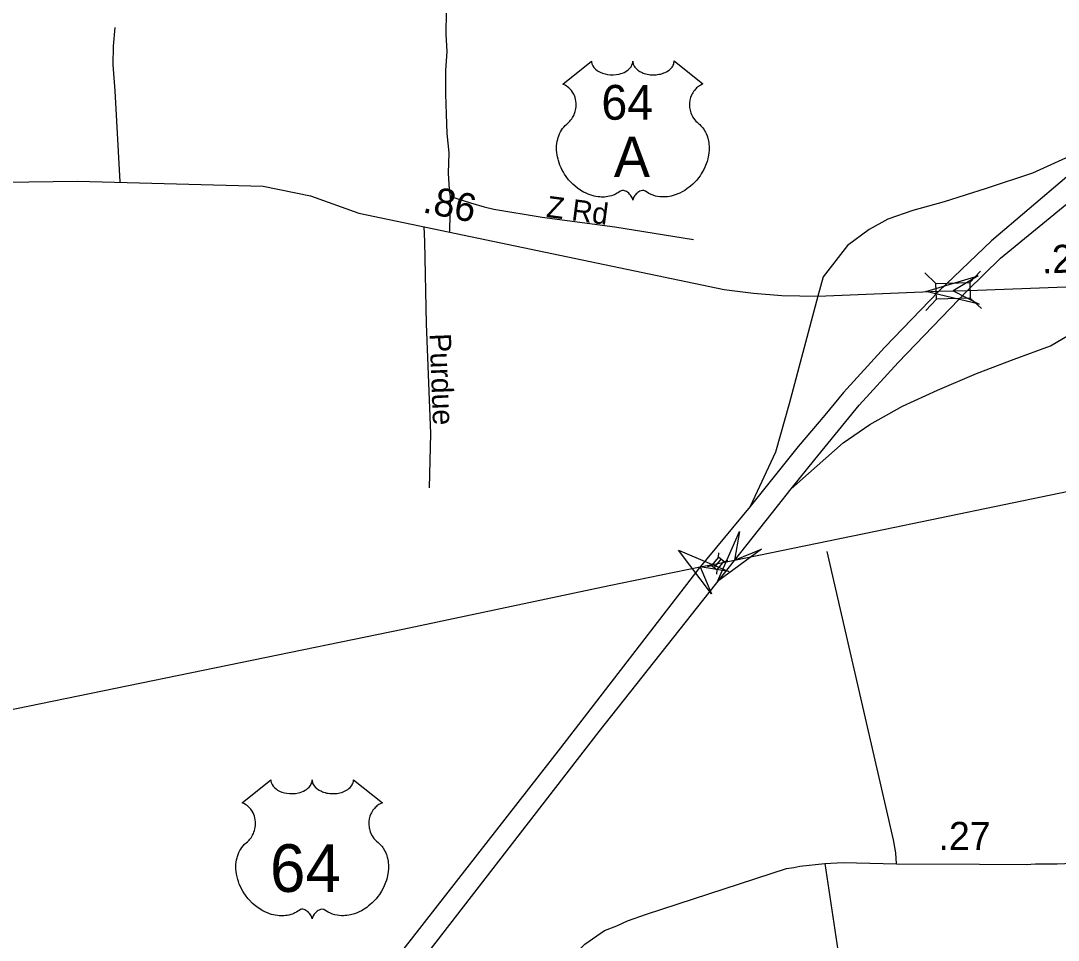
# Model space of a CAD drawing. Extents: x 2220236 to 2384410, y 720751 to 894131.
# Drawn here: x 2294303 to 2298927, y 806601 to 810700 of the extents above; entities that cross this region are included whole.
import ezdxf

# ---------------------------------------------------------------- set-up
doc = ezdxf.new("R2010")
doc.units = 0
for name, color, linetype in [('Exist Railroad Mainline', 7, 'Continuous'), ('Exist Road Non-System Type 51', 7, 'Continuous'), ('Exist Road Non-System Type 51 Label', 7, 'Continuous'), ('Exist Road Primary Interstate Structure Standard Bridge CELL', 7, 'Continuous'), ('Exist Road Primary US Attributed', 7, 'Continuous'), ('Exist Road Primary US Divided Attributed', 7, 'Continuous'), ('Exist Road Primary US Mileage Hundredths English Label', 7, 'Continuous'), ('Exist Road Primary US Ramp 1 Lane  Attributed', 7, 'Continuous'), ('Exist Road Primary US Shield CELL', 7, 'Continuous'), ('Exist Road Primary US Shield Number Label', 7, 'Continuous'), ('Exist Road Primary US Structure Standard Bridge CELL', 7, 'Continuous'), ('Exist Road Secondary Mileage Hundredths English Label', 7, 'Continuous'), ('Exist Road Secondary Structure Standard Bridge Attributed CELL', 7, 'Continuous'), ('Exist Road Secondary Type 10 Attributed', 7, 'Continuous'), ('Exist Road Secondary Type 51 Attributed', 7, 'Continuous')]:
    doc.layers.add(name, color=color, linetype=linetype)

msp = doc.modelspace()

# ---------------------------------------------------------------- linework, layer by layer
at = {"layer": 'Exist Railroad Mainline'}
for points in [[(2297485.2, 808295.4), (2298113, 808425.3), (2299547.1, 808722.5), (2300514.6, 808918.9), (2300696.2, 808954.7), (2300734.1, 808967.3), (2300795.9, 808977.8), (2300861.9, 808984.5), (2300935.6, 808997.3), (2301005.4, 809006.2), (2301137.4, 809017.6), (2301359.2, 809029.8), (2301569, 809020.2), (2302025, 809015), (2302689, 808990.3), (2303650.7, 808970.6)], [(2293833.8, 807542.5), (2296006.8, 807988.7), (2296926.1, 808182.5), (2297331, 808265.1), (2297409.9, 808280.9), (2297485.2, 808295.4)]]:
    msp.add_lwpolyline(points, dxfattribs=at)
at = {"layer": 'Exist Road Non-System Type 51'}
msp.add_line((2296216.3, 809760.3), (2296218.4, 809916.5), dxfattribs=at)
for points in [[(2296218.4, 809916.5), (2296214.2, 809948.2), (2296210, 810020), (2296212.1, 810110.8), (2296203.7, 810197.4), (2296201.5, 810284), (2296197.3, 810372.7), (2296197.3, 810478.3), (2296203.7, 810562.7), (2296199.4, 810638.8), (2296200.5, 810743.3), (2296200.5, 810853.1), (2296187.8, 810962.9), (2296187.8, 811102.3), (2296194.2, 811174.1)], [(2294722, 810669.4), (2294714.7, 810587.4), (2294713.5, 810503.4), (2294722.5, 810387.5), (2294744.4, 809981.9)], [(2296218.4, 809916.5), (2296308.1, 809889), (2296368.3, 809869.9), (2296412.5, 809860.3), (2296626.6, 809824.6), (2296951.1, 809782), (2297302.1, 809725.4)], [(2296099.2, 809782.4), (2296102.4, 809713.8), (2296110.8, 809348.5), (2296129.8, 808860.7), (2296123.5, 808617.8)], [(2298207.1, 806942.5), (2298202.9, 806990.4), (2298193.8, 807048.8), (2297897.3, 808333.8)]]:
    msp.add_lwpolyline(points, dxfattribs=at)
at = {"layer": 'Exist Road Primary Interstate Structure Standard Bridge CELL'}
for p, q in [((2297412.7, 808309.2), (2297413.9, 808328)), ((2297364.5, 808267.5), (2297382.6, 808272.4)), ((2297394.9, 808262.5), (2297424.9, 808299.3)), ((2297436.9, 808289.5), (2297455.1, 808294.4)), ((2297406, 808233.7), (2297407.1, 808252.5))]:
    msp.add_line(p, q, dxfattribs=at)
msp.add_lwpolyline([(2297407.1, 808252.5), (2297437.1, 808289.3), (2297412.6, 808309.3), (2297382.6, 808272.4)], close=True, dxfattribs=at)
at = {"layer": 'Exist Road Primary US Attributed'}
for points in [[(2293904.9, 809976.1), (2294556.5, 809984.2), (2295384.3, 809961.9), (2295594.6, 809920), (2295810.1, 809841.6), (2297438.2, 809502.6), (2297569.1, 809485.9), (2297694.7, 809475.5), (2297855.3, 809472.6)], [(2298523.1, 809497.7), (2298568.2, 809499.7), (2299158.2, 809521.6)], [(2297855.3, 809472.6), (2298395.9, 809494)], [(2298395.9, 809494), (2298523.1, 809497.7)]]:
    msp.add_lwpolyline(points, dxfattribs=at)
at = {"layer": 'Exist Road Primary US Divided Attributed'}
for points in [[(2298523.1, 809497.7), (2298670.5, 809641.9), (2298997.8, 809910.4), (2299400.8, 810227.6), (2299931.3, 810641.7), (2299997.6, 810692.7)], [(2299383.2, 810331.2), (2299279.4, 810251.2), (2298965.8, 810004.9), (2298630.2, 809719.7), (2298395.9, 809494)], [(2298395.9, 809494), (2298153.6, 809243.9), (2297970.5, 809042.9), (2297886.8, 808942.4), (2297768.4, 808802.1), (2297554.6, 808534.5)], [(2297737.2, 808613.5), (2297841.8, 808743.7), (2298039.4, 808985.8), (2298214.6, 809176.9), (2298523.1, 809497.7)], [(2292591.9, 803356.2), (2293003.8, 803603.7), (2293502.9, 803938), (2293873.3, 804224), (2294268.5, 804550.7), (2294566.7, 804812.2), (2294779.9, 805007.5), (2294960, 805191.9), (2295496.1, 805770.5), (2295825.1, 806169.5), (2295961.2, 806343.1), (2296881.9, 807531.7), (2297484.3, 808293.7), (2297675.7, 808536.8), (2297737.2, 808613.5)], [(2297554.6, 808534.5), (2297325.3, 808258.3), (2296708.4, 807459), (2296006.3, 806558.7), (2295742, 806239.7), (2295563.6, 806033.3), (2295375.7, 805844.1), (2294851.6, 805335.4), (2294464.3, 804991.8), (2294032.3, 804624.2), (2293708.3, 804361.4), (2293414.3, 804136), (2293195.3, 803978.7), (2292893.8, 803772.9), (2292502.5, 803515.4), (2292211.3, 803330.5), (2291723.5, 803055.3), (2291280.6, 802811.1), (2290605.7, 802486.4)]]:
    msp.add_lwpolyline(points, dxfattribs=at)
at = {"layer": 'Exist Road Primary US Ramp 1 Lane  Attributed'}
for points in [[(2299383.2, 810331.2), (2298976.8, 810095.4), (2298813.3, 810019.9), (2298606.7, 809951.5), (2298419.4, 809893.5), (2298279.7, 809854.8), (2298168.2, 809816.2), (2298084.9, 809770), (2297988.3, 809698.7), (2297879.9, 809558.6), (2297855.3, 809472.6)], [(2297737.2, 808613.5), (2297968.2, 808818.1), (2298087.9, 808899.9), (2298233.6, 808981.7), (2298389.7, 809053.1), (2298563.6, 809127.5), (2298731.5, 809190.9), (2298892.9, 809250.9), (2298976.1, 809300), (2299031.1, 809344.6), (2299144.1, 809471.1), (2299158.2, 809521.6)], [(2297855.3, 809472.6), (2297728.2, 808992.1), (2297667.2, 808776.4), (2297554.6, 808534.5)]]:
    msp.add_lwpolyline(points, dxfattribs=at)
at = {"layer": 'Exist Road Primary US Shield CELL'}
for points in [[(2296847.4, 810520.2), (2296847.7, 810514.8), (2296849, 810508.5), (2296850, 810505.3), (2296853, 810499), (2296857.8, 810491.7), (2296864.6, 810484.4), (2296872.3, 810478.1), (2296877.5, 810474.8), (2296886.2, 810470.1), (2296896.2, 810465.9), (2296907.3, 810462.7), (2296918.6, 810460.4), (2296931, 810459.1), (2296943.2, 810458.8), (2296956.4, 810459.8), (2296971, 810462.6), (2296977.8, 810464.4), (2296985.3, 810467), (2296992.3, 810469.9), (2296999.9, 810474), (2297006.1, 810477.9), (2297010.9, 810481.4), (2297017.7, 810487.9), (2297023.2, 810494.7), (2297025.5, 810498.5), (2297027.4, 810502.1), (2297030.1, 810509.9), (2297030.9, 810513.3), (2297031.4, 810520.4), (2297031.9, 810514.5), (2297032.5, 810510.7), (2297033.5, 810507.1), (2297035, 810503.2), (2297037.7, 810497.7), (2297040.8, 810493.2), (2297046.5, 810486.4), (2297050.1, 810483.1), (2297053.3, 810480.4), (2297062.1, 810474.4), (2297072.3, 810469.2), (2297077.3, 810467), (2297082.4, 810465.2), (2297089, 810463.2), (2297095.7, 810461.6), (2297102.4, 810460.5), (2297109.3, 810459.5), (2297116.2, 810459), (2297121.9, 810458.8), (2297128.9, 810458.9), (2297135.4, 810459.3), (2297142, 810460.1), (2297149.3, 810461.3), (2297155.1, 810462.6), (2297162.9, 810464.6), (2297169.9, 810467.1), (2297176, 810469.8), (2297184, 810474), (2297190.4, 810478), (2297195.2, 810481.8), (2297200.8, 810487), (2297206.1, 810493.1), (2297209.2, 810497.6), (2297211.4, 810502.2), (2297213.5, 810507.1), (2297214.7, 810512.3), (2297215.3, 810516.7), (2297215.4, 810520.6), (2297344, 810418.1), (2297341, 810417), (2297334, 810413.5), (2297328.5, 810410.3), (2297319.6, 810404), (2297315.8, 810400.6), (2297312, 810397.1), (2297308.5, 810393.3), (2297305.5, 810389.7), (2297301.7, 810384.5), (2297298.4, 810379.4), (2297295.1, 810373.7), (2297292.7, 810368.7), (2297288.8, 810358.4), (2297286.9, 810351.8), (2297285.7, 810346.3), (2297284.2, 810334.8), (2297283.8, 810329.4), (2297283.8, 810324), (2297284.1, 810318.3), (2297284.6, 810312.8), (2297285.6, 810307.1), (2297286.5, 810302.1), (2297288.1, 810295.9), (2297290.4, 810288.8), (2297293.2, 810281.9), (2297299.1, 810270.7), (2297306.6, 810259.3), (2297312, 810252.9), (2297317.4, 810247.4), (2297325.3, 810240.8), (2297329.6, 810237), (2297334.5, 810232), (2297342.6, 810222.7), (2297345.8, 810218.3), (2297349.1, 810213.3), (2297352.2, 810208.2), (2297355.2, 810202.8), (2297357.6, 810198), (2297362.2, 810187), (2297365.5, 810176.2), (2297367, 810170.6), (2297369.4, 810158), (2297370.3, 810151.8), (2297371.3, 810139.5), (2297371.3, 810124.6), (2297370.2, 810110.4), (2297367.5, 810093.9), (2297365.3, 810084.1), (2297361.9, 810072.6), (2297358.7, 810062.6), (2297352.8, 810048), (2297347.6, 810037.3), (2297340.8, 810024.9), (2297336.2, 810017.4), (2297330.8, 810009.3), (2297324, 810000), (2297316.1, 809990.1), (2297306.6, 809979.7), (2297299, 809972.1), (2297288.9, 809963.1), (2297282.9, 809958.1), (2297274.2, 809951.5), (2297262.4, 809943.6), (2297250.7, 809936.9), (2297240.7, 809931.8), (2297231.9, 809928), (2297220.5, 809923.7), (2297201.5, 809918.4), (2297194.6, 809917), (2297186.4, 809915.8), (2297178.8, 809915), (2297171.3, 809914.5), (2297161.3, 809914.5), (2297151.3, 809915.3), (2297141.9, 809916.7), (2297132.1, 809918.7), (2297121.9, 809921.8), (2297112.6, 809925.4), (2297103.1, 809930), (2297087.2, 809940.1), (2297082.6, 809942.5), (2297080.1, 809943.2), (2297073.9, 809943.5), (2297068.1, 809942.3), (2297062.2, 809939.9), (2297058.6, 809938), (2297053.9, 809934.9), (2297050.2, 809932), (2297045.8, 809927.8), (2297042.8, 809924.3), (2297040.5, 809921.6), (2297036, 809914.5), (2297034.4, 809911.2), (2297032.7, 809906.9), (2297031.3, 809900.5), (2297029.2, 809908.5), (2297026.9, 809913.9), (2297024.2, 809918.4), (2297021.3, 809922.4), (2297016.8, 809927.6), (2297012.8, 809931.5), (2297007.9, 809935.4), (2297002.8, 809938.6), (2296998.6, 809940.7), (2296994.8, 809942.1), (2296990.2, 809943.3), (2296986.4, 809943.6), (2296983.3, 809943.5), (2296979, 809942.5), (2296973.2, 809938.3), (2296967.7, 809934.5), (2296961.7, 809930.8), (2296954.6, 809927), (2296949.3, 809924.6), (2296943.1, 809922.1), (2296935.8, 809919.7), (2296927.9, 809917.7), (2296919.8, 809916.1), (2296912.6, 809914.9), (2296905, 809914.2), (2296898.1, 809914), (2296890.8, 809914.1), (2296884.1, 809914.6), (2296876.3, 809915.3), (2296866.5, 809916.7), (2296858.5, 809918.6), (2296850, 809920.8), (2296841.2, 809923.6), (2296831.9, 809927.2), (2296820.2, 809932.2), (2296812.1, 809936.4), (2296799.2, 809943.8), (2296784.2, 809954.2), (2296772.9, 809963.4), (2296764.5, 809970.9), (2296752.3, 809983.4), (2296745.1, 809991.5), (2296733.9, 810006.1), (2296726.6, 810016.7), (2296722, 810024.4), (2296715.1, 810036.9), (2296711.4, 810044.7), (2296706.5, 810056.1), (2296702.7, 810066.5), (2296699.5, 810076.4), (2296697.8, 810082.7), (2296695.3, 810093.7), (2296693.9, 810101.5), (2296692.4, 810112.3), (2296691.6, 810123.6), (2296691.5, 810134), (2296691.7, 810142.7), (2296692.7, 810152.8), (2296694.4, 810163.5), (2296696.5, 810172.7), (2296698.4, 810179.3), (2296701.1, 810187.3), (2296704.7, 810196.2), (2296708.9, 810204.7), (2296713, 810211.8), (2296718.1, 810219.4), (2296723.1, 810225.9), (2296729.7, 810233), (2296736.5, 810239.5), (2296742.8, 810244.6), (2296750.2, 810251.9), (2296754.1, 810256.3), (2296758.8, 810262.5), (2296762.5, 810268.2), (2296765.5, 810273.3), (2296769.4, 810280.8), (2296771.7, 810286.4), (2296774.7, 810295.1), (2296776.2, 810301.2), (2296777.7, 810309), (2296778.7, 810316.4), (2296779, 810325.6), (2296778.8, 810333.2), (2296777.8, 810342), (2296776.2, 810350.6), (2296774.1, 810358), (2296771, 810366.5), (2296768, 810372.7), (2296763.1, 810381.2), (2296757.6, 810389), (2296752, 810395.4), (2296746.3, 810401.1), (2296740.8, 810405.3), (2296735.6, 810409.1), (2296729.1, 810413), (2296722.8, 810416.1), (2296718.8, 810417.7)], [(2295418.3, 807316.1), (2295418.6, 807310.8), (2295419.9, 807304.5), (2295420.9, 807301.2), (2295423.8, 807295), (2295428.7, 807287.6), (2295435.5, 807280.4), (2295443.2, 807274.1), (2295448.3, 807270.7), (2295457.1, 807266), (2295467, 807261.8), (2295478.1, 807258.7), (2295489.5, 807256.4), (2295501.8, 807255), (2295514.1, 807254.8), (2295527.3, 807255.8), (2295541.9, 807258.6), (2295548.6, 807260.3), (2295556.1, 807262.9), (2295563.1, 807265.8), (2295570.8, 807269.9), (2295576.9, 807273.8), (2295581.8, 807277.3), (2295588.6, 807283.9), (2295594, 807290.6), (2295596.3, 807294.4), (2295598.3, 807298.1), (2295601, 807305.8), (2295601.7, 807309.3), (2295602.3, 807316.4), (2295602.7, 807310.4), (2295603.3, 807306.7), (2295604.3, 807303), (2295605.8, 807299.2), (2295608.6, 807293.7), (2295611.6, 807289.1), (2295617.3, 807282.4), (2295620.9, 807279), (2295624.2, 807276.4), (2295632.9, 807270.4), (2295643.1, 807265.2), (2295648.1, 807263), (2295653.3, 807261.2), (2295659.8, 807259.2), (2295666.6, 807257.6), (2295673.3, 807256.4), (2295680.1, 807255.5), (2295687.1, 807254.9), (2295692.8, 807254.8), (2295699.8, 807254.9), (2295706.2, 807255.2), (2295712.9, 807256), (2295720.1, 807257.2), (2295726, 807258.5), (2295733.7, 807260.6), (2295740.7, 807263.1), (2295746.9, 807265.7), (2295754.9, 807269.9), (2295761.3, 807273.9), (2295766, 807277.7), (2295771.6, 807282.9), (2295777, 807289), (2295780.1, 807293.5), (2295782.3, 807298.2), (2295784.3, 807303), (2295785.6, 807308.2), (2295786.2, 807312.7), (2295786.3, 807316.5), (2295914.9, 807214.1), (2295911.9, 807212.9), (2295904.9, 807209.5), (2295899.3, 807206.2), (2295890.5, 807200), (2295886.7, 807196.6), (2295882.9, 807193), (2295879.4, 807189.2), (2295876.3, 807185.6), (2295872.6, 807180.5), (2295869.3, 807175.3), (2295866, 807169.6), (2295863.6, 807164.7), (2295859.7, 807154.3), (2295857.8, 807147.8), (2295856.5, 807142.2), (2295855, 807130.8), (2295854.6, 807125.3), (2295854.6, 807119.9), (2295855, 807114.2), (2295855.5, 807108.7), (2295856.5, 807103), (2295857.4, 807098), (2295859, 807091.9), (2295861.3, 807084.7), (2295864.1, 807077.8), (2295869.9, 807066.6), (2295877.5, 807055.2), (2295882.9, 807048.9), (2295888.2, 807043.4), (2295896.2, 807036.7), (2295900.4, 807032.9), (2295905.4, 807028), (2295913.4, 807018.6), (2295916.7, 807014.2), (2295920, 807009.3), (2295923, 807004.2), (2295926.1, 806998.7), (2295928.5, 806993.9), (2295933, 806982.9), (2295936.3, 806972.2), (2295937.8, 806966.6), (2295940.2, 806953.9), (2295941.2, 806947.7), (2295942.1, 806935.4), (2295942.2, 806920.5), (2295941, 806906.4), (2295938.4, 806889.9), (2295936.2, 806880), (2295932.8, 806868.5), (2295929.5, 806858.6), (2295923.6, 806843.9), (2295918.4, 806833.3), (2295911.7, 806820.8), (2295907.1, 806813.3), (2295901.7, 806805.2), (2295894.9, 806796), (2295887, 806786.1), (2295877.5, 806775.7), (2295869.8, 806768), (2295859.8, 806759), (2295853.7, 806754), (2295845.1, 806747.5), (2295833.2, 806739.6), (2295821.5, 806732.8), (2295811.6, 806727.7), (2295802.8, 806723.9), (2295791.4, 806719.6), (2295772.4, 806714.4), (2295765.5, 806712.9), (2295757.3, 806711.7), (2295749.6, 806710.9), (2295742.2, 806710.5), (2295732.1, 806710.5), (2295722.2, 806711.2), (2295712.8, 806712.6), (2295703, 806714.7), (2295692.7, 806717.7), (2295683.4, 806721.3), (2295674, 806726), (2295658.1, 806736), (2295653.5, 806738.4), (2295650.9, 806739.1), (2295644.8, 806739.4), (2295639, 806738.2), (2295633.1, 806735.9), (2295629.5, 806734), (2295624.8, 806730.8), (2295621.1, 806728), (2295616.7, 806723.8), (2295613.7, 806720.3), (2295611.4, 806717.5), (2295606.9, 806710.5), (2295605.3, 806707.1), (2295603.6, 806702.8), (2295602.1, 806696.4), (2295600.1, 806704.5), (2295597.8, 806709.8), (2295595, 806714.4), (2295592.2, 806718.4), (2295587.7, 806723.6), (2295583.7, 806727.4), (2295578.8, 806731.4), (2295573.6, 806734.5), (2295569.5, 806736.6), (2295565.7, 806738.1), (2295561.1, 806739.2), (2295557.3, 806739.5), (2295554.2, 806739.4), (2295549.9, 806738.5), (2295544.1, 806734.3), (2295538.6, 806730.5), (2295532.6, 806726.7), (2295525.4, 806722.9), (2295520.2, 806720.5), (2295513.9, 806718.1), (2295506.7, 806715.6), (2295498.8, 806713.6), (2295490.6, 806712), (2295483.5, 806710.9), (2295475.8, 806710.2), (2295468.9, 806709.9), (2295461.7, 806710), (2295454.9, 806710.6), (2295447.1, 806711.2), (2295437.4, 806712.7), (2295429.3, 806714.5), (2295420.8, 806716.8), (2295412.1, 806719.5), (2295402.8, 806723.1), (2295391.1, 806728.2), (2295382.9, 806732.4), (2295370.1, 806739.7), (2295355.1, 806750.1), (2295343.7, 806759.3), (2295335.4, 806766.9), (2295323.2, 806779.3), (2295316, 806787.5), (2295304.7, 806802), (2295297.5, 806812.6), (2295292.8, 806820.4), (2295286, 806832.8), (2295282.2, 806840.6), (2295277.4, 806852), (2295273.5, 806862.5), (2295270.4, 806872.3), (2295268.6, 806878.6), (2295266.2, 806889.7), (2295264.7, 806897.5), (2295263.3, 806908.2), (2295262.5, 806919.5), (2295262.3, 806929.9), (2295262.6, 806938.6), (2295263.6, 806948.7), (2295265.3, 806959.4), (2295267.4, 806968.6), (2295269.2, 806975.2), (2295271.9, 806983.3), (2295275.6, 806992.2), (2295279.8, 807000.7), (2295283.9, 807007.7), (2295289, 807015.3), (2295294, 807021.8), (2295300.5, 807028.9), (2295307.4, 807035.5), (2295313.6, 807040.6), (2295321.1, 807047.9), (2295325, 807052.3), (2295329.6, 807058.4), (2295333.4, 807064.1), (2295336.3, 807069.2), (2295340.2, 807076.7), (2295342.6, 807082.4), (2295345.5, 807091), (2295347, 807097.1), (2295348.5, 807104.9), (2295349.5, 807112.3), (2295349.9, 807121.5), (2295349.7, 807129.1), (2295348.7, 807138), (2295347, 807146.5), (2295345, 807153.9), (2295341.8, 807162.4), (2295338.9, 807168.7), (2295334, 807177.1), (2295328.5, 807184.9), (2295322.8, 807191.3), (2295317.1, 807197), (2295311.7, 807201.3), (2295306.5, 807205), (2295299.9, 807209), (2295293.6, 807212.1), (2295289.7, 807213.7)]]:
    msp.add_lwpolyline(points, close=True, dxfattribs=at)
at = {"layer": 'Exist Road Primary US Structure Standard Bridge CELL'}
for p, q in [((2298332.5, 809576.9), (2298382.5, 809529.4)), ((2298533.6, 809533), (2298581.1, 809583.1)), ((2298336.9, 809408.8), (2298384.4, 809458.9)), ((2298535.4, 809464.1), (2298585.4, 809416.6))]:
    msp.add_line(p, q, dxfattribs=at)
msp.add_lwpolyline([(2298382.5, 809529.4), (2298533.6, 809533.4), (2298535.4, 809462.8), (2298384.4, 809458.9)], close=True, dxfattribs=at)
at = {"layer": 'Exist Road Secondary Structure Standard Bridge Attributed CELL'}
for points in [[(2298575, 809436.7), (2298337.7, 809492.8), (2298571.2, 809562.9), (2298459.5, 809496.4)], [(2297605.4, 808344.7), (2297409, 808200.3), (2297506.9, 808423.6), (2297485.2, 808295.4)], [(2297382.5, 808145.7), (2297234.4, 808339.5), (2297459.5, 808245.7), (2297331, 808265.1)]]:
    msp.add_lwpolyline(points, close=True, dxfattribs=at)
at = {"layer": 'Exist Road Secondary Type 10 Attributed'}
msp.add_lwpolyline([(2297887, 806943.5), (2297958.2, 806468.5), (2297979.4, 806356.7), (2297986.1, 806284.8), (2297979.8, 806126.9), (2297976.4, 806078.7), (2297965.4, 805978.6), (2297958.6, 805860.7), (2297953.4, 805802.7), (2297935.3, 805624.5), (2297922.4, 805528.5), (2297909, 805460.4), (2297879.8, 805396.1), (2297866.2, 805356), (2297862.5, 805333.8), (2297860.8, 805301.9), (2297873.9, 805196), (2297870.5, 805134.1), (2297846.8, 804935.8), (2297839.9, 804819.9)], dxfattribs=at)
at = {"layer": 'Exist Road Secondary Type 51 Attributed'}
for points in [[(2295752, 804871.8), (2296033.4, 805350.3), (2296722.8, 806475), (2296748.3, 806511.3), (2296773.9, 806541.6), (2296817.6, 806584.2), (2296904.7, 806644.9), (2296960.5, 806665.6), (2297008.2, 806688.2), (2297091.8, 806717), (2297715.5, 806921.5), (2297749.3, 806925.9), (2297775.3, 806932.2), (2297887, 806943.5)], [(2297887, 806943.5), (2297969.4, 806947.2), (2298207.1, 806942.5), (2298576.7, 806940.9), (2298784.7, 806939.2), (2298826.6, 806941.5), (2298922.6, 806942.6), (2299130.5, 806950.9), (2299158.4, 806955.1), (2299316.5, 806967.1)]]:
    msp.add_lwpolyline(points, dxfattribs=at)

# ---------------------------------------------------------------- texts
at = {"layer": 'Exist Road Non-System Type 51 Label'}
for s, rotation, p in [('Z Rd', 352.5314, (2296642.6, 809825.7)), ('Purdue', 272.1484, (2296125.5, 809305))]:
    msp.add_text(s, height=95, rotation=rotation, dxfattribs=at).set_placement(p)
at = {"layer": 'Exist Road Primary US Mileage Hundredths English Label'}
for s, rotation, p in [('.86', 348.2407, (2296090.5, 809847)), ('.23', 2.1314, (2298855.6, 809572.9))]:
    msp.add_text(s, height=125, rotation=rotation, dxfattribs=at).set_placement(p)
at = {"layer": 'Exist Road Primary US Shield Number Label'}
for s, height, p in [('64', 155, (2296891.2, 810258.8)), ('A', 180, (2296947, 810004)), ('64', 212.5, (2295414, 806816.8))]:
    msp.add_text(s, height=height, dxfattribs=at).set_placement(p)
at = {"layer": 'Exist Road Secondary Mileage Hundredths English Label'}
msp.add_text('.27', height=125, rotation=359.7517, dxfattribs=at).set_placement((2298393.5, 807004.2))

doc.saveas('drawing.dxf')
